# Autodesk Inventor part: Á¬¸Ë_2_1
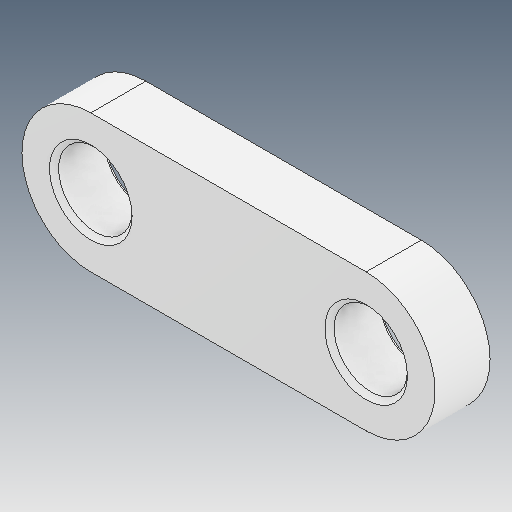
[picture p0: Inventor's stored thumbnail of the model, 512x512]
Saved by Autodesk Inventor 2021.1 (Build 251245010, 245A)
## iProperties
Created: 2021-05
Part Number: Á¬¸Ë_2_1
Material: Ogólny
Document SubType Name: Modeling
Designer: user
Density: 1 g/cm^3
Appearance: Domyślna
Author: user
Revision Number: ÈÎºÎ
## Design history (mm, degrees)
feature "ÊäÈë1"
node "Bryła1"
